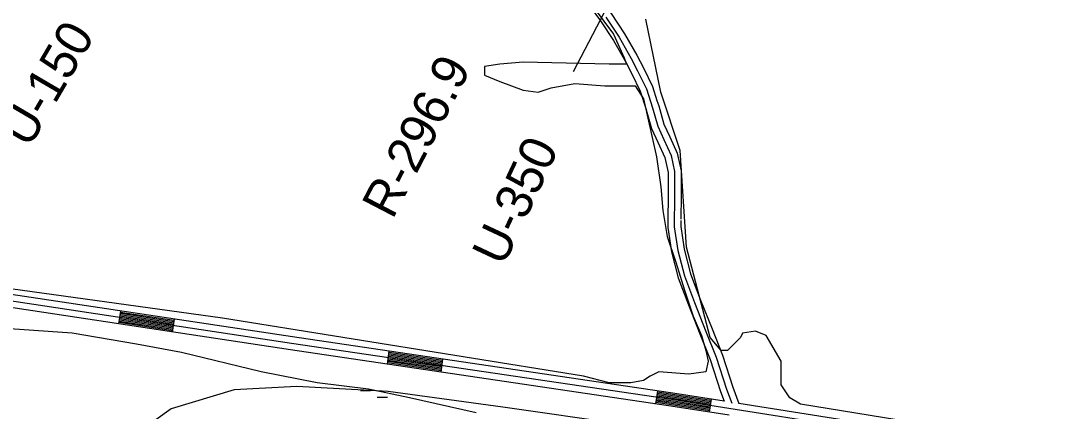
# Model space of a CAD drawing. Extents: x 3161615 to 3199515, y 867541 to 892976.
# Drawn here: x 3183730 to 3186134, y 876681 to 877578 of the extents above; entities that cross this region are included whole.
import ezdxf

# ---------------------------------------------------------------- set-up
doc = ezdxf.new("R2010")
doc.units = 0
for name, color, linetype in [('V-RIVR-RANG', 7, 'Continuous'), ('V-RIVR-RANG-IDEN', 7, 'Continuous'), ('V-ROAD-CNTR', 7, 'Continuous'), ('V-SITE-VEGE', 7, 'Continuous'), ('V-WETL-SWMP', 7, 'Continuous')]:
    doc.layers.add(name, color=color, linetype=linetype)

msp = doc.modelspace()

# ---------------------------------------------------------------- linework, layer by layer
at = {"layer": 'V-RIVR-RANG'}
msp.add_line((3185002.7, 877462), (3186543.4, 880415.3), dxfattribs=at)
at = {"layer": 'V-ROAD-CNTR'}
for p, q in [((3183955.8, 876881), (3183960.2, 876910.7)), ((3184079.4, 876862.3), (3184083.8, 876892)), ((3184573.9, 876788.4), (3184578.3, 876818.1)), ((3184697.6, 876770.1), (3184701.9, 876799.8)), ((3185192.2, 876697), (3185196.6, 876726.7)), ((3185315.6, 876678), (3185320.3, 876707.6))]:
    msp.add_line(p, q, dxfattribs=at)
for points in [[(3185007.4, 877708.3), (3185031.5, 877675.2), (3185058.7, 877636.8), (3185089.5, 877595.1), (3185120.1, 877548.3), (3185148.4, 877498.9), (3185163.6, 877469.9), (3185184.2, 877427.5), (3185194.7, 877395)], [(3184991.3, 877679.5), (3185007.1, 877657.7), (3185034.4, 877619.2), (3185064.9, 877578), (3185094.5, 877532.6), (3185122.1, 877484.5), (3185136.8, 877456.3), (3185156.3, 877416.3), (3185170, 877373.9)], [(3185077.2, 877586.5), (3185107.3, 877540.5), (3185135.2, 877491.7), (3185150.2, 877463.1), (3185170.3, 877421.9), (3185184.4, 877378.2), (3185196.5, 877335.7), (3185210.2, 877305.1), (3185227, 877268.7), (3185235.2, 877231.3), (3185235.3, 877176.1), (3185234.4, 877104), (3185242.6, 877050.1), (3185257.8, 876991.7), (3185281, 876930.2), (3185307.5, 876863.9), (3185331.3, 876804.3), (3185355.1, 876730.7), (3185366.7, 876698.7)], [(3185194.7, 877395), (3185198.7, 877382.5), (3185210.6, 877340.8), (3185223.9, 877311.4), (3185241.3, 877273.5), (3185250.1, 877233), (3185250.3, 877176), (3185249.6, 877121.7)], [(3185170, 877373.9), (3185170, 877373.8), (3185182.3, 877330.5), (3185196.6, 877298.9), (3185212.7, 877263.9), (3185220.2, 877229.7), (3185220.3, 877176.2), (3185219.6, 877118.6)], [(3185349.2, 876703.1), (3185241.1, 876720.1), (3184355.3, 876851), (3183436.7, 876989.7), (3183098.8, 877042.5), (3182834.6, 877082.7), (3182622.7, 877117), (3182567.2, 877122.2), (3182524.7, 877121.8), (3182470.4, 877122.4), (3181711.3, 877125.1), (3181651.7, 877130.2)], [(3185219.6, 877118.6), (3185219.4, 877103), (3185227.8, 877047), (3185243.5, 876987.1), (3185267, 876924.8), (3185293.6, 876858.4), (3185317.2, 876799.2), (3185340.9, 876725.9), (3185349.2, 876703.1)], [(3185249.6, 877118.7), (3185249.4, 877105), (3185257.3, 877053.1), (3185272.1, 876996.2), (3185295, 876935.6), (3185321.4, 876869.5), (3185345.5, 876809.4), (3185369.3, 876735.6), (3185383, 876697.7)], [(3185360.9, 876670.9), (3185236.6, 876690.5), (3184350.8, 876821.3), (3183432.2, 876960.1), (3183094.2, 877012.9), (3182830, 877053.1), (3182619, 877087.2), (3182566, 877092.1), (3182524.6, 877091.8), (3182470.2, 877092.4), (3181709.9, 877095.1), (3181683.2, 877097.4), (3181638.4, 877102.4)], [(3187217.2, 876379.5), (3186063.7, 876575.2), (3185238.8, 876705.3), (3184353.1, 876836.2), (3183434.5, 876974.9), (3183096.5, 877027.7), (3182832.3, 877067.9), (3182620.8, 877102.1), (3182566.6, 877107.2), (3182524.7, 877106.8), (3182470.3, 877107.4), (3181710.6, 877110.1), (3181684.7, 877112.3), (3181660.7, 877115)], [(3184082.9, 876886.1), (3183959.3, 876904.7)], [(3184083.4, 876889), (3183959.8, 876907.7)], [(3184079.8, 876865.3), (3183956.2, 876884)], [(3184080.2, 876868.3), (3183956.6, 876886.9)], [(3184080.7, 876871.2), (3183957.1, 876889.9)], [(3184081.1, 876874.2), (3183957.5, 876892.9)], [(3184081.6, 876877.2), (3183958, 876895.8)], [(3184082, 876880.1), (3183958.4, 876898.8)], [(3184082.5, 876883.1), (3183958.9, 876901.8)], [(3184700.2, 876787.9), (3184576.5, 876806.2)], [(3184700.6, 876790.9), (3184577, 876809.2)], [(3184701.1, 876793.9), (3184577.4, 876812.1)], [(3184701.5, 876796.8), (3184577.8, 876815.1)], [(3184698, 876773.1), (3184574.3, 876791.4)], [(3184698.4, 876776), (3184574.8, 876794.3)], [(3184698.9, 876779), (3184575.2, 876797.3)], [(3184699.3, 876782), (3184575.7, 876800.3)], [(3184699.7, 876785), (3184576.1, 876803.2)], [(3185317.9, 876692.8), (3185238.8, 876705.3), (3185194.4, 876711.9)], [(3185318.4, 876695.8), (3185239.3, 876708.3), (3185194.8, 876714.8)], [(3185318.9, 876698.8), (3185239.8, 876711.2), (3185195.3, 876717.8)], [(3185319.3, 876701.7), (3185240.2, 876714.2), (3185195.7, 876720.8)], [(3185319.8, 876704.7), (3185240.7, 876717.2), (3185196.1, 876723.7)], [(3185316, 876681), (3185237, 876693.4), (3185192.6, 876700)], [(3185316.5, 876683.9), (3185237.5, 876696.4), (3185193.1, 876703)], [(3185317, 876686.9), (3185237.9, 876699.4), (3185193.5, 876705.9)], [(3185317.4, 876689.9), (3185238.4, 876702.3), (3185193.9, 876708.9)], [(3187219.7, 876394.3), (3186066.1, 876590), (3185383, 876697.7)]]:
    msp.add_lwpolyline(points, dxfattribs=at)
at = {"layer": 'V-SITE-VEGE'}
for p, q in [((3183848, 876859.6), (3183704.5, 876869.5)), ((3183996.4, 876834.8), (3183848, 876859.6)), ((3184100.3, 876815), (3183996.4, 876834.8)), ((3184283.3, 876770.5), (3184100.3, 876815)), ((3184412, 876745.8), (3184283.3, 876770.5)), ((3184530.7, 876730.9), (3184412, 876745.8)), ((3184624.7, 876711.1), (3184530.7, 876730.9)), ((3184778.1, 876676.5), (3184624.7, 876711.1))]:
    msp.add_line(p, q, dxfattribs=at)
for points in [[(3185050.2, 877607), (3185094.7, 877547.6), (3185119.4, 877493.2), (3185124.4, 877478.3), (3185084.8, 877478.3), (3184886.9, 877483.3), (3184832.5, 877478.3), (3184797.9, 877473.4), (3184797.9, 877453.6), (3184832.5, 877438.7), (3184886.9, 877418.9), (3184921.5, 877414), (3184951.2, 877423.9), (3185005.7, 877433.8), (3185074.9, 877428.8)], [(3187657.4, 876349.8), (3185525.1, 876696.3), (3185500.4, 876711.1), (3185480.6, 876740.8), (3185480.6, 876795.2), (3185446, 876854.6), (3185421.2, 876864.5), (3185391.5, 876859.6), (3185386.6, 876849.7), (3185356.9, 876820), (3185342.1, 876820), (3185317.3, 876849.7), (3185262.9, 877057.6), (3185248.1, 877280.3), (3185203.5, 877414), (3185168.9, 877582.3)], [(3185074.9, 877428.8), (3185144.2, 877428.8), (3185164, 877399.1), (3185193.6, 877265.5), (3185203.5, 877196.2), (3185208.5, 877141.7), (3185218.4, 877082.3), (3185238.2, 877022.9), (3185258, 876958.6), (3185277.8, 876899.2), (3185297.5, 876854.6), (3185307.4, 876820), (3185312.4, 876795.2), (3185307.4, 876770.5), (3185267.9, 876765.5), (3185198.6, 876770.5), (3185178.8, 876760.6), (3185164, 876750.7), (3185134.3, 876745.7), (3185084.8, 876745.7), (3185025.4, 876760.6), (3184194.3, 876894.2), (3183511.5, 876988.3)]]:
    msp.add_lwpolyline(points, dxfattribs=at)
at = {"layer": 'V-WETL-SWMP'}
for p, q in [((3184365.9, 876736.8), (3184221.2, 876729.5)), ((3184575.7, 876725.9), (3184365.9, 876736.8)), ((3184221.2, 876729.5), (3184076.5, 876686.1)), ((3184512.2, 876728.1), (3184535, 876728)), ((3184550.1, 876712.5), (3184574.1, 876712.5)), ((3184839.8, 876689.7), (3184575.7, 876725.9)), ((3184076.5, 876686.1), (3184041.2, 876660.4)), ((3185118.3, 876649.9), (3184839.8, 876689.7))]:
    msp.add_line(p, q, dxfattribs=at)

# ---------------------------------------------------------------- texts
at = {"layer": 'V-RIVR-RANG-IDEN'}
for s, rotation, p in [('U-150', 59.6551, (3183749.3, 877283.4)), ('R-296.9', 62.5467, (3184586, 877119.4)), ('U-350', 64.8893, (3184841.3, 877011.2))]:
    msp.add_text(s, height=83, rotation=rotation, dxfattribs=at).set_placement(p)

doc.saveas('drawing.dxf')
